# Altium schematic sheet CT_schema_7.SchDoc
size 277 x 170 mm
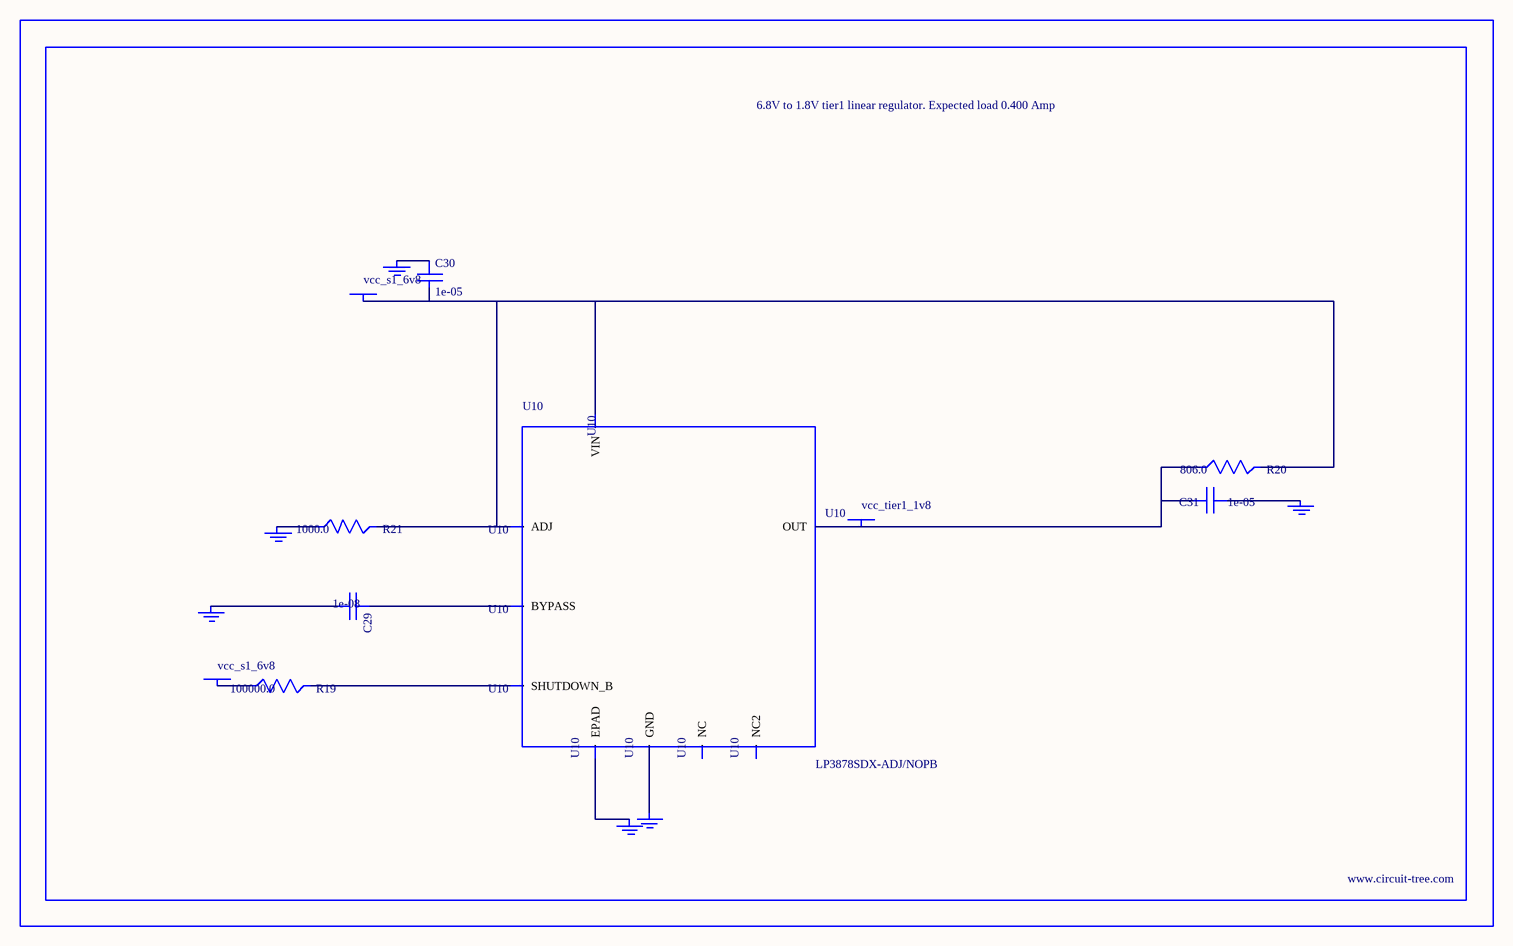
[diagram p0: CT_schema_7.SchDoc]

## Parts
BORDER6  (no value)
C29  1e-08  [C0402]
C30  1e-05  [C1206]
C31  1e-05  [C0805]
GND_INSTANCE_6_0  (no value)
GND_INSTANCE_6_1  (no value)
GND_INSTANCE_6_2  (no value)
GND_INSTANCE_6_3  (no value)
GND_INSTANCE_6_4  (no value)
GND_INSTANCE_6_5  (no value)
POWER_INSTANCE_6_0  vcc_s1_6v8
POWER_INSTANCE_6_1  vcc_s1_6v8
POWER_INSTANCE_6_2  vcc_tier1_1v8
R19  100000.0  [R0603]
R20  806.0  [R0603]
R21  1000.0  [R0603]
U10  LP3878SDX-ADJ/NOPB  [WSON-8]

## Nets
NetC29_1: C29.1 U10.1(BYPASS)
NetC29_2: C29.2 GND_INSTANCE_6_0.0(GND)
NetC30_1: C30.1 GND_INSTANCE_6_1.0(GND)
NetC30_2: C30.2 POWER_INSTANCE_6_0.0(PWR) R20.2 R21.2 U10.4(VIN) U10.6(ADJ)
NetC31_1: C31.1 GND_INSTANCE_6_2.0(GND)
NetC31_2: C31.2 POWER_INSTANCE_6_2.0(PWR) R20.1 U10.5(OUT)
NetGND_INSTANCE_6_3_0: GND_INSTANCE_6_3.0(GND) R21.1
NetGND_INSTANCE_6_4_0: GND_INSTANCE_6_4.0(GND) U10.PAD(EPAD)
NetGND_INSTANCE_6_5_0: GND_INSTANCE_6_5.0(GND) U10.3(GND)
NetPOWER_INSTANCE_6_1_0: POWER_INSTANCE_6_1.0(PWR) R19.1
NetR19_2: R19.2 U10.8(SHUTDOWN_B)

Not connected (* = marked no-connect by the designer): U10 2(NC) 7(NC2)

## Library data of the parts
BORDER6 = BORDER_PAGE6
C29 = C0402C103K3RAC
C30 = C1206C106K3RACTU
C31 = GRM219R60J106ME19D
GND_INSTANCE_6_0-GND_INSTANCE_6_5 = GND
POWER_INSTANCE_6_0-POWER_INSTANCE_6_2 = PWR
R19 = RC0603JR-07100KL
R20 = ERJ-3EKF8060V
R21 = RC0603JR-071KL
